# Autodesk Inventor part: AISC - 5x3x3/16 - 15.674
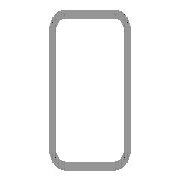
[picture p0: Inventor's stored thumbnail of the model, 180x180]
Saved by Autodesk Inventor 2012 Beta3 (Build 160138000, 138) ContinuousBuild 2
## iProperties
_CCFamilyMember: 33
_CCFamilyDisplayName: ANSI AISC (Rectangular) - Tube
_FrameMemberDoc: Frame Member File
_Version: 15.0.0
_GetPNFromCC: 1
Created: 2010-11
Part Number: AISC - 5x3x3/16 - 15.674
Material: Steel, Mild
Description: Tube
Document SubType Name: Modeling
Standard: ANSI
Designer: Beta-8540w
Standards Organization: ANSI
Language: en-US
Size Designation: 5x3x3/16
Categories: <MemberInstance><Categories><Category DisplayName="Structural Shapes" InternalName="089c4875-fa83-4c05-b084-43b9cc11f5ed" Mnemonic="GRDR"><CategoryParameter Dis
Stock Number: 5x3x3/16
Density: 7.86 g/cm^3
IsCustomPart: 1
G_W: 3.000 in
G_H: 5.000 in
G_L: 15.674 in
+56B78839-94CC-4781-8179-10EE230693A1+CUTDETAIL1: Cut
+31F04844-9E02-49A4-9EBC-19785BF63232+CUTDETAIL2: Cut
Author: Beta-8540w
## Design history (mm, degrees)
node "Start plane"
node "End plane"
sketch "Sketch"
  geometry: L1 (-38.1, -53.975)-(-38.1, 53.975); L2 (-28.575, 63.5)-(28.575, 63.5); L3 (38.1, 53.975)-(38.1, -53.975); L4 (28.575, -63.5)-(-28.575, -63.5); L5 (-28.575, 58.737)-(28.575, 58.737); L6 (33.338, 53.975)-(33.338, -53.975); L7 (28.575, -58.737)-(-28.575, -58.737); L8 (-33.338, -53.975)-(-33.338, 53.975); L9 (0, 91.662)-(0, -91.662) reference; L10 (-56.102, 0)-(56.102, 0) reference; A1 r 9.525 centre (-28.575, -53.975) between (-38.1, -53.975) and (-28.575, -63.5); A2 r 9.525 centre (-28.575, 53.975) between (-28.575, 63.5) and (-38.1, 53.975); A3 r 9.525 centre (28.575, 53.975) between (38.1, 53.975) and (28.575, 63.5); A4 r 9.525 centre (28.575, -53.975) between (28.575, -63.5) and (38.1, -53.975); A5 r 4.763 centre (-28.575, 53.975) between (-28.575, 58.737) and (-33.338, 53.975); A6 r 4.763 centre (28.575, 53.975) between (33.338, 53.975) and (28.575, 58.737); A7 r 4.763 centre (28.575, -53.975) between (28.575, -58.737) and (33.338, -53.975); A8 r 4.763 centre (-28.575, -53.975) between (-33.338, -53.975) and (-28.575, -58.737)
  constraints: 16 end point, 16 point on circle, 8 centre point, 8 tangent, 4 parallel, 3 equal radius, 2 perpendicular, 7 other
  dimensions: "d10" = 127 distance between parallel lines of L2 L4 (= G_H); "d11" = 76.2 distance between parallel lines of L1 L3 (= G_W); "d12" = 4.7625 distance between parallel lines of L3 L6 (= G_T); "d15" = 63.5 distance between parallel lines of L2 L10 (= 0.5 x d10); "d16" = 38.1 distance between parallel lines of L9 L3 (= 0.5 x d11); "d17" = 9.525 radius of A1 (= G_IR)
extrude "Body" new body sketch "Sketch" stored distance "d3" = 398.12556 (= G_L); taper "d4" = 0 deg
node "Driven Length"
  sketch "Sketch3"
    geometry: L1 (0, 0)-(10, 0) reference
    constraints: 2 end point, 1 horizontal
  workplane "Work Plane3"
  sketch "Sketch4"
    geometry: L1 (-2, 25.924)-(12, 25.924) reference; L2 (-2, 424.049)-(12, 424.049) reference
    dimensions: "d19" = 398.12556 distance between parallel lines of L1 L2 (derived)
workplane "Work Plane4"
split "Split1"
workplane "Work Plane5"
split "Split2"
body "Solid1"
other parameters: "G_W" = 76.2 [user parameter; used in 1 equation term], "G_H" = 127 [user parameter; used in 1 equation term], "G_T" = 4.7625 [user parameter; used in 1 equation term], "G_IR" = 9.525 [user parameter; used in 1 equation term], "G_L" = 398.12556 (= d19) [user parameter; used in 1 equation term], "G_OFFSET_START" = -25.92377 [user parameter; used in 1 equation term], "G_OFFSET_END" = -25.92377 [user parameter; used in 1 equation term], "d13" = 25.92377 (= -G_OFFSET_START), "d14" = 424.04933 (= G_OFFSET_END + B_L), "B_L" = 449.97309 [user parameter; used in 1 equation term], "d18" = 90 deg
